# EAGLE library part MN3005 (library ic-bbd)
4096-Stage Long Delay BBD
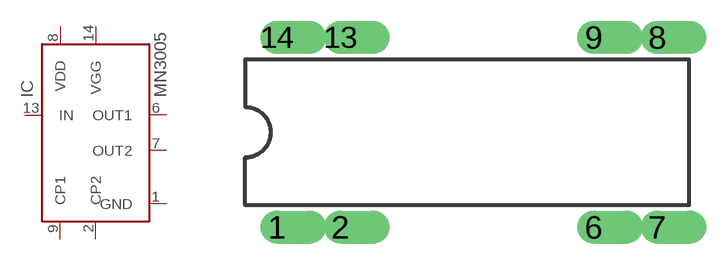
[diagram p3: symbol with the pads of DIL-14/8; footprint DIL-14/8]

Designator prefix IC

## MN3005  [DIL-14/8]
1  GND
2  CP2
6  OUT1
7  OUT2
8  VDD
9  CP1
13  IN
14  VGG

## Footprint DIL-14/8 (pad centres in mm)
Dual In Line Package
drill 0.813 offset: 1 -7.62,-3.81; 2 -5.08,-3.81; 6 5.08,-3.81; 7 7.62,-3.81; 8 7.62,3.81; 9 5.08,3.81; 13 -5.08,3.81; 14 -7.62,3.81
